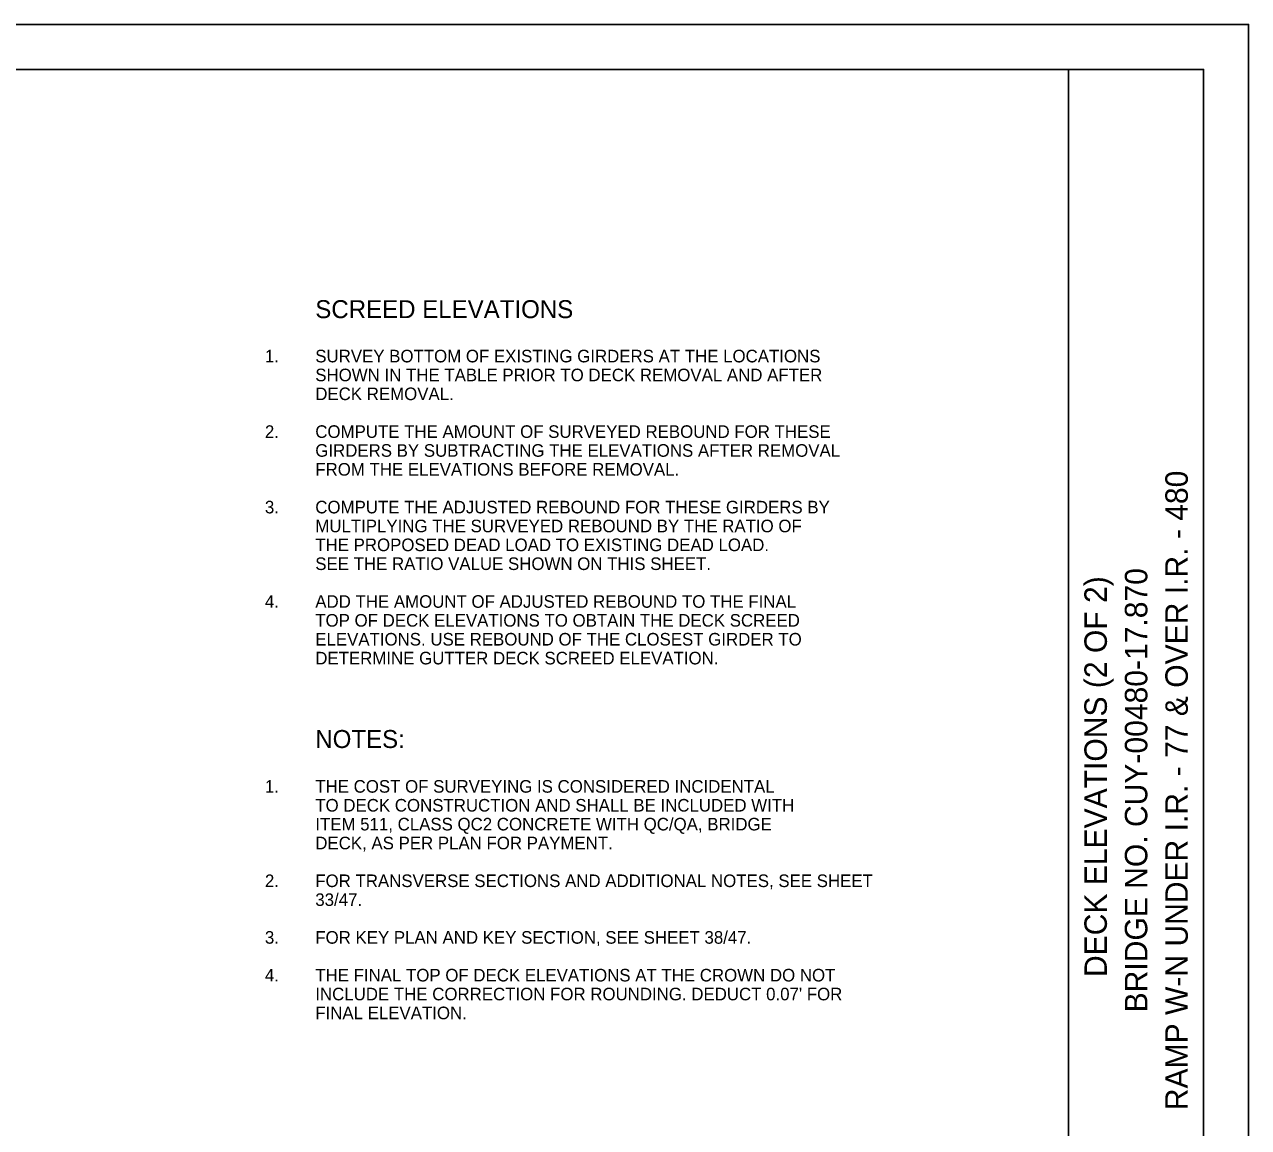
# Model space of a CAD drawing. Extents: x 0 to 34, y 0 to 22.
# Drawn here: x 20.39 to 34, y 9.73 to 22 of the extents above; entities that cross this region are included whole.
import ezdxf

# ---------------------------------------------------------------- set-up
doc = ezdxf.new("R2010")
doc.units = 0
for name, color, linetype in [('BR_P_Gen_Text', 7, 'Continuous'), ('SH_Border', 7, 'Continuous'), ('SH_Cut_Line', 7, 'Continuous'), ('SH_Data', 7, 'Continuous')]:
    doc.layers.add(name, color=color, linetype=linetype)

msp = doc.modelspace()

# ---------------------------------------------------------------- linework, layer by layer
at = {"layer": 'SH_Border'}
msp.add_line((32, 0.5), (32, 21.5), dxfattribs=at)
msp.add_lwpolyline([(1.5, 21.5), (33.5, 21.5), (33.5, 0.5), (1.5, 0.5)], close=True, dxfattribs=at)
at = {"layer": 'SH_Cut_Line'}
msp.add_lwpolyline([(0, 0), (34, 0), (34, 22), (0, 22)], close=True, dxfattribs=at)

# ---------------------------------------------------------------- texts
at = {"layer": 'BR_P_Gen_Text'}
for s, height, p in [('SCREED ELEVATIONS', 0.2, (23.623, 18.733)), ('1.   ', 0.14, (23.063, 18.241)), ('SURVEY BOTTOM OF EXISTING GIRDERS AT THE LOCATIONS ', 0.14, (23.623, 18.241)), ('SHOWN IN THE TABLE PRIOR TO DECK REMOVAL AND AFTER ', 0.14, (23.623, 18.031)), ('DECK REMOVAL.', 0.14, (23.623, 17.821)), ('2.   ', 0.14, (23.063, 17.401)), ('COMPUTE THE AMOUNT OF SURVEYED REBOUND FOR THESE', 0.14, (23.623, 17.401)), ('GIRDERS BY SUBTRACTING THE ELEVATIONS AFTER REMOVAL', 0.14, (23.623, 17.191)), ('FROM THE ELEVATIONS BEFORE REMOVAL.', 0.14, (23.623, 16.981)), ('3.   ', 0.14, (23.063, 16.561)), ('COMPUTE THE ADJUSTED REBOUND FOR THESE GIRDERS BY', 0.14, (23.623, 16.561)), ('MULTIPLYING THE SURVEYED REBOUND BY THE RATIO OF', 0.14, (23.623, 16.351)), ('THE PROPOSED DEAD LOAD TO EXISTING DEAD LOAD.', 0.14, (23.623, 16.141)), ('SEE THE RATIO VALUE SHOWN ON THIS SHEET.', 0.14, (23.623, 15.931)), ('ADD THE AMOUNT OF ADJUSTED REBOUND TO THE FINAL', 0.14, (23.623, 15.511)), ('4.   ', 0.14, (23.063, 15.511)), ('TOP OF DECK ELEVATIONS TO OBTAIN THE DECK SCREED', 0.14, (23.623, 15.301)), ('ELEVATIONS. USE REBOUND OF THE CLOSEST GIRDER TO', 0.14, (23.623, 15.091)), ('DETERMINE GUTTER DECK SCREED ELEVATION.', 0.14, (23.623, 14.881)), ('NOTES:', 0.2, (23.623, 13.951)), ('1.', 0.14, (23.063, 13.454)), ('THE COST OF SURVEYING IS CONSIDERED INCIDENTAL', 0.14, (23.623, 13.454)), ('TO DECK CONSTRUCTION AND SHALL BE INCLUDED WITH', 0.14, (23.623, 13.244)), ('ITEM 511, CLASS QC2 CONCRETE WITH QC/QA, BRIDGE', 0.14, (23.623, 13.034)), ('DECK, AS PER PLAN FOR PAYMENT.', 0.14, (23.623, 12.824)), ('2.   ', 0.14, (23.063, 12.404)), ('FOR TRANSVERSE SECTIONS AND ADDITIONAL NOTES, SEE SHEET', 0.14, (23.623, 12.404)), ('33/47.', 0.14, (23.623, 12.194)), ('3.', 0.14, (23.063, 11.774)), ('FOR KEY PLAN AND KEY SECTION, SEE SHEET 38/47.', 0.14, (23.623, 11.774)), ('4.', 0.14, (23.063, 11.354)), ('THE FINAL TOP OF DECK ELEVATIONS AT THE CROWN DO NOT', 0.14, (23.623, 11.354)), ("INCLUDE THE CORRECTION FOR ROUNDING. DEDUCT 0.07' FOR", 0.14, (23.623, 11.144)), ('FINAL ELEVATION.', 0.14, (23.623, 10.934))]:
    msp.add_text(s, height=height, dxfattribs=at).set_placement(p)
at = {"layer": 'SH_Data'}
for s, p in [('RAMP W-N UNDER I.R. - 77 & OVER I.R. - 480', (33.325, 9.922)), ('BRIDGE NO. CUY-00480-17.870', (32.875, 11.01)), ('DECK ELEVATIONS (2 OF 2)', (32.425, 11.403))]:
    msp.add_text(s, height=0.25, rotation=90, dxfattribs=at).set_placement(p)

doc.saveas('drawing.dxf')
